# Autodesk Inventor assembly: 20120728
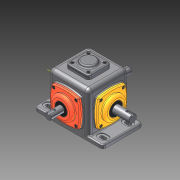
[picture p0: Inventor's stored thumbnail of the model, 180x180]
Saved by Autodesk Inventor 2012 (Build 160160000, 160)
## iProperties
Created: 2012-07
Part Number: 20120728
Document SubType Name: Assembly
Designer: JANG KYOUNG-IL
Author: JANG KYOUNG-IL
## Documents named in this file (16)
- C:\Users\mdu1\Desktop\2012-07-28-출제문제\20120728.iam
- C:\Users\mdu1\Desktop\2012-07-28-출제문제\1-본체.ipt
- C:\Users\mdu1\Desktop\2012-07-28-출제문제\2-메인커버.ipt
- C:\Users\mdu1\Desktop\2012-07-28-출제문제\3-서브커버.ipt
- C:\Users\mdu1\Desktop\2012-07-28-출제문제\3-서브커버_MIR.ipt
- C:\Users\mdu1\Desktop\2012-07-28-출제문제\공용품\4-메인축[구동부].ipt
- C:\Users\mdu1\Desktop\2012-07-28-출제문제\공용품\5-서브축.ipt
- C:\Users\mdu1\Desktop\2012-07-28-출제문제\공용품\6-베벨기어1.ipt
- C:\Users\mdu1\Desktop\2012-07-28-출제문제\공용품\7-베벨기어2.ipt
- C:\Users\mdu1\Desktop\2012-07-28-출제문제\공용품\8-베어링 6203.ipt
- C:\Users\mdu1\Desktop\2012-07-28-출제문제\공용품\9-베어링 6204.ipt
- C:\Users\mdu1\Desktop\2012-07-28-출제문제\공용품\10-오일실-1.ipt
- C:\Users\mdu1\Desktop\2012-07-28-출제문제\공용품\11-오일실-2.ipt
- C:\Users\mdu1\Desktop\2012-07-28-출제문제\공용품\12-키 4x4.ipt
- C:\Users\mdu1\Desktop\2012-07-28-출제문제\공용품\13-M4.ipt
- C:\Users\mdu1\Desktop\2012-07-28-출제문제\공용품\14-뚜껑.ipt
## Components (33 placed, 13 different names)
1. 1-본체:1
2. 2-메인커버:1
3. 3-서브커버:1
4. 3-서브커버_MIR:1
5. 4-메인축[구동부]:1
6. 5-서브축:1
7. 5-서브축:2
8. 14-뚜껑:1
9. 12-키 4x4:1
10. 12-키 4x4:3
11. 12-키 4x4:4
12. KS B 2023 6203 - 17 x 40 x 12:1
13. KS B 2023 6204 - 20 x 47 x 14:1
14. KS B 2804 D D - 20 35 8:1
15. KS B 2804 D D - 17 32 8:1
16. KS B 2804 D D - 17 32 8:2
17. KS B 2023 6203 - 17 x 40 x 12:2
18. KS B 1003 - 미터 M 4 x 10:14
19. KS B 1003 - 미터 M 4 x 10:15
20. KS B 1003 - 미터 M 4 x 10:16
21. KS B 1003 - 미터 M 4 x 10:17
22. KS B 1003 - 미터 M 4 x 10:1
23. KS B 1003 - 미터 M 4 x 10:2
24. KS B 1003 - 미터 M 4 x 10:3
25. KS B 1003 - 미터 M 4 x 10:4
26. KS B 1003 - 미터 M 4 x 10:5
27. KS B 1003 - 미터 M 4 x 10:8
28. KS B 1003 - 미터 M 4 x 10:9
29. KS B 1003 - 미터 M 4 x 10:10
30. KS B 1003 - 미터 M 4 x 10:7
31. KS B 1003 - 미터 M 4 x 10:11
32. KS B 1003 - 미터 M 4 x 10:12
33. KS B 1003 - 미터 M 4 x 10:13
